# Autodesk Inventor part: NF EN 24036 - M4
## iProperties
Created: 2007-08
Part Number: NF EN 24036 - M4
Material: Stahl, weich, unlegiert
Description: Sechskantmutter
Vendor: Autodesk Inc.
Document SubType Name: Modeling
Standard: NF EN 24036
Designer: Ulrich
Standards Organization: AFNOR
Language: de-DE
Size Designation: M4
Categories: <MemberInstance Version="R10.0.0"><Categories><Category DisplayName="Schrauben" InternalName="e4da775c-781d-43d5-af7c-5136215cf5a6" Mnemonic="FSTN"><Category Di
Author: Ulrich
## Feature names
1. Körper [Extrusion]
2. Gewinde [Hole]
3. Fase2 [Chamfer]
4. Fase1 [Chamfer]
